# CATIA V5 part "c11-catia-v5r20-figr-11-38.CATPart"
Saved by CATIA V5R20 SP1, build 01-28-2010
Part number: Part1
Bounding box of the stored display mesh (mm): x -82.6 to 82.6, y -78 to 78, z 0 to 136
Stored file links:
  D:\v5_r20\psrt_files_downloaded\c11\c11-catia-v5r20-figr-11-38.CATPart
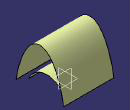
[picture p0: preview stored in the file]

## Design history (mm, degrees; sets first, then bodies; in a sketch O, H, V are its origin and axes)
Set1
  Extrude1: Element1 Sketch1, Lim1 59, Lim2 59, Direction yz-plane
  Affinity1: ToTransfor Extrude1, RatioX 1.4, RatioY 1.3, RatioZ 3.4
Body1 (main body)
  Sketch1 on yz-plane, origin (0, 0, 0), H (0, 1, 0), V (0, 0, 1)
    arc A1 centre (0, -25) radius 65 from (-60, 0) to (60, 0) cw
    point P2 (-60, 0)
    point P3 (60, 0)
    coincidence: P2 H, P3 H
